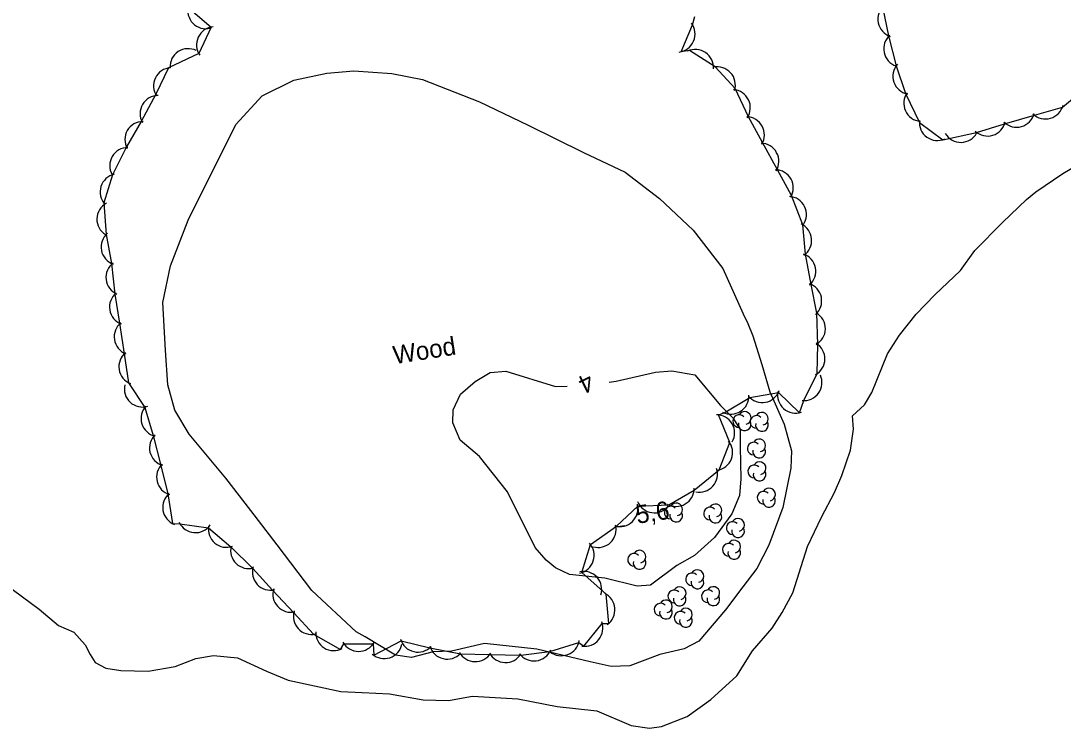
# Model space of a CAD drawing. Extents: x 643342 to 646936, y 5873857 to 5876103.
# Drawn here: x 643552.1 to 643724.9, y 5875255.8 to 5875373.1 of the extents above; entities that cross this region are included whole.
import ezdxf

# ---------------------------------------------------------------- set-up
doc = ezdxf.new("R2010")
doc.units = 0
for name, color, linetype in [('Niveau 2', 7, 'Continuous'), ('Niveau 3', 7, 'Continuous'), ('Niveau 4', 7, 'Continuous'), ('Niveau 44', 7, 'Continuous')]:
    doc.layers.add(name, color=color, linetype=linetype)

msp = doc.modelspace()

# ---------------------------------------------------------------- linework, layer by layer
at = {"layer": 'Niveau 2'}
for points in [[(643607.66, 5875271.79), (643600.32, 5875278.65), (643594.57, 5875286.24), (643590.17, 5875291.92), (643586.04, 5875297.27), (643579.96, 5875304.59), (643577.6, 5875308.55), (643576.42, 5875312.72), (643576.05, 5875318.5), (643575.62, 5875326.41), (643576.88, 5875332.45), (643579.8, 5875340.05), (643587.72, 5875355.89), (643592.06, 5875360.65), (643597.3, 5875363.22), (643602.78, 5875364.39), (643607.26, 5875364.77), (643613.59, 5875364.35), (643618.66, 5875363.35), (643628.11, 5875359.64), (643636.16, 5875355.81), (643645.33, 5875351.24), (643652.26, 5875348.02), (643657.97, 5875343.64), (643663.53, 5875338.4), (643668.46, 5875332.05), (643671.84, 5875324.5), (643672.57, 5875322.9)], [(643672.57, 5875322.9), (643673.45, 5875320.84), (643674.93, 5875316.1), (643676.26, 5875311.58), (643678.62, 5875306.2), (643679.83, 5875301.79), (643679.71, 5875298.93), (643678.37, 5875292.41), (643676.05, 5875286.16), (643674.11, 5875282.32), (643671.76, 5875279.27), (643668.87, 5875275.47), (643664.45, 5875270.23), (643662.06, 5875268.97), (643657.98, 5875268.03), (643653.03, 5875266.19), (643649.95, 5875266.06), (643646.44, 5875266.83), (643637.59, 5875268.94), (643628.96, 5875269.88), (643623.49, 5875268.6), (643620.41, 5875268.46), (643616.81, 5875267.56), (643614.17, 5875267.94), (643609.16, 5875270.96), (643607.66, 5875271.79)], [(643643.03, 5875281.28), (643640.68, 5875282.39), (643639.15, 5875283.68), (643637.31, 5875285.78), (643632.73, 5875295), (643628.08, 5875300.89), (643624.89, 5875303.58), (643623.7, 5875306.45), (643623.76, 5875308.58), (643624.96, 5875311.17), (643627.39, 5875313.27), (643629.87, 5875314.78), (643632.46, 5875315), (643640.73, 5875312.49), (643642.65, 5875312.55)], [(643663.81, 5875314.42), (643668.04, 5875309.33), (643670.12, 5875307.25), (643671.35, 5875305.34), (643671.35, 5875302.49), (643671.45, 5875297.17), (643671.21, 5875294.42), (643669.93, 5875291.35), (643667.06, 5875287.44), (643663.75, 5875284.43), (643660.81, 5875282.77), (643656.46, 5875279.56), (643654.22, 5875279.37), (643648.89, 5875280.7), (643643.03, 5875281.28)], [(643649.62, 5875313.19), (643650.74, 5875313.33), (643657.26, 5875314.82), (643659.97, 5875315.05), (643663.81, 5875314.42)]]:
    msp.add_lwpolyline(points, dxfattribs=at)
at = {"layer": 'Niveau 3'}
msp.add_line((643651.42, 5875289.29), (643652.21, 5875289.41), dxfattribs=at)
msp.add_line((643651.42, 5875289.29), (643652.21, 5875289.41), dxfattribs=at)
at = {"layer": 'Niveau 4'}
for points in [[(643691.93, 5875309.45), (643693.18, 5875311.46), (643695.73, 5875317.86), (643697.73, 5875320.99), (643700.53, 5875324.44), (643703.58, 5875327.66), (643707.88, 5875331.71), (643710.22, 5875335), (643714.82, 5875339.66), (643718.78, 5875343.44), (643720.34, 5875344.76), (643724.84, 5875347.75), (643728.46, 5875349.95)], [(643544.82, 5875283.14), (643555.09, 5875275.56), (643558.29, 5875272.86), (643560.87, 5875271.77), (643562.72, 5875269.66), (643563.56, 5875268.07), (643564.39, 5875266.71), (643566.13, 5875265.79), (643568.66, 5875265.41), (643573.19, 5875265.31), (643577.64, 5875266.04), (643581.09, 5875267.39), (643584.02, 5875267.88), (643587.98, 5875267.49), (643592.8, 5875265.28), (643596.37, 5875263.8), (643605.09, 5875261.91), (643608.68, 5875261.73), (643613.21, 5875261.52), (643618.76, 5875260.55), (643622.94, 5875260.43), (643626.92, 5875261.12), (643629.79, 5875261), (643634.45, 5875260.67), (643640.98, 5875259.44), (643647.58, 5875258.68), (643653.26, 5875256.3), (643656.27, 5875255.84), (643658.27, 5875256.12), (643662.53, 5875257.79), (643666.45, 5875260.61), (643670.76, 5875264.53), (643673.38, 5875268.68), (643676.64, 5875272.4), (643678.31, 5875275.03), (643680.06, 5875278.27), (643682.5, 5875285.96), (643684.83, 5875290.79), (643686.98, 5875294.89), (643688.16, 5875297.73), (643689.6, 5875301.89), (643690.13, 5875305.38), (643689.94, 5875307.62), (643691.93, 5875309.45)]]:
    msp.add_lwpolyline(points, dxfattribs=at)
at = {"layer": 'Niveau 44'}
for points in [[(643693.89, 5875400.62), (643694.24, 5875395.35), (643694.29, 5875390.5), (643694.26, 5875385.36), (643694.18, 5875380.51), (643694.94, 5875375.38), (643695.89, 5875370.62), (643697.19, 5875365.62), (643698.75, 5875361.02), (643701.03, 5875356.25), (643704.95, 5875353.38), (643710.53, 5875354.58), (643715.17, 5875356.01), (643720.11, 5875357.46), (643724.77, 5875358.79), (643728.77, 5875362.1)], [(643579.79, 5875375.28), (643583.61, 5875372.05), (643581.57, 5875367.65), (643576.54, 5875365.27), (643574.42, 5875360.9), (643572.01, 5875356.38), (643569.57, 5875352.18), (643567.26, 5875347.55), (643565.8, 5875342.92), (643566.2, 5875337.64), (643567.08, 5875332.87), (643567.65, 5875327.76), (643568.4, 5875322.97), (643569.19, 5875317.88), (643569.94, 5875313.09), (643572.6, 5875308.99), (643574, 5875304.34), (643575.29, 5875299.37), (643576.43, 5875294.66), (643577.23, 5875289.74), (643578.45, 5875289.69), (643583.16, 5875289.03), (643586.87, 5875285.9), (643590.51, 5875282.29), (643593.81, 5875278.73), (643597.3, 5875274.96), (643600.6, 5875271.4), (643605.06, 5875268.89), (643605.62, 5875269.81), (643610.48, 5875269.79), (643610.56, 5875267.91), (643615.13, 5875270.29), (643619.85, 5875269.16), (643624.93, 5875268.16), (643629.79, 5875268.02), (643634.97, 5875267.94), (643639.78, 5875268.52), (643644.58, 5875270.06), (643645.39, 5875269.41), (643648.46, 5875273.18), (643649.53, 5875273.2), (643649.12, 5875278.03), (643645.06, 5875281.63)], [(643645.06, 5875281.63), (643646.52, 5875286.26), (643650.84, 5875289.29), (643654.34, 5875292.65), (643659.5, 5875292.85), (643663.7, 5875295.28), (643667.85, 5875298.64), (643669.59, 5875303.17), (643667.72, 5875307.78), (643668.69, 5875308.08), (643672.91, 5875310.64), (643677.69, 5875311.5), (643681.17, 5875308.12), (643681.9, 5875310.13), (643684.09, 5875314.6), (643684.18, 5875319.45), (643684.05, 5875324.64), (643683.09, 5875329.4), (643682.14, 5875334.42), (643681.72, 5875339.26), (643679.84, 5875344.11), (643677.51, 5875348.37), (643675.05, 5875352.89), (643672.72, 5875357.15), (643670.47, 5875361.85), (643667.19, 5875365.43), (643662.9, 5875368.16), (643661.52, 5875367.96), (643663.41, 5875372.43)], [(643663.41, 5875372.43), (643663.82, 5875373.78)]]:
    msp.add_lwpolyline(points, dxfattribs=at)
for centre, radius, start, end in [((643582.74, 5875374.77), 3, 164.1537, 284.1317), ((643582.74, 5875374.77), 3, 164.1537, 284.1317), ((643582.74, 5875374.77), 3, 164.1537, 284.1317), ((643697.15, 5875373.35), 3, 131.2961, 251.274), ((643697.15, 5875373.35), 3, 131.2961, 251.274), ((643697.15, 5875373.35), 3, 131.2961, 251.274), ((643660.84, 5875370.88), 3, 277.0845, 37.0624), ((643660.84, 5875370.88), 3, 277.0845, 37.0624), ((643660.84, 5875370.88), 3, 277.0845, 37.0624), ((643584.19, 5875369.11), 3, 95.0938, 215.0717), ((643584.19, 5875369.11), 3, 95.0938, 215.0717), ((643584.19, 5875369.11), 3, 95.0938, 215.0717), ((643698.12, 5875368.44), 3, 131.2961, 251.274), ((643698.12, 5875368.44), 3, 131.2961, 251.274), ((643698.12, 5875368.44), 3, 131.2961, 251.274), ((643579.79, 5875365.47), 3, 63.1855, 183.1634), ((643579.79, 5875365.47), 3, 63.1855, 183.1634), ((643579.79, 5875365.47), 3, 63.1855, 183.1634), ((643663.9, 5875365.34), 3, 355.5807, 115.5586), ((643663.9, 5875365.34), 3, 355.5807, 115.5586), ((643663.9, 5875365.34), 3, 355.5807, 115.5586), ((643699.64, 5875363.89), 3, 138.696, 258.674), ((643699.64, 5875363.89), 3, 138.696, 258.674), ((643699.64, 5875363.89), 3, 138.696, 258.674), ((643577.07, 5875362.31), 3, 94.1708, 214.1488), ((643577.07, 5875362.31), 3, 94.1708, 214.1488), ((643577.07, 5875362.31), 3, 94.1708, 214.1488), ((643667.53, 5875362.45), 3, 342.4524, 102.4304), ((643667.53, 5875362.45), 3, 342.4524, 102.4304), ((643667.53, 5875362.45), 3, 342.4524, 102.4304), ((643574.83, 5875357.71), 3, 89.7917, 209.7696), ((643574.83, 5875357.71), 3, 89.7917, 209.7696), ((643574.83, 5875357.71), 3, 89.7917, 209.7696), ((643670.01, 5875358.68), 3, 325.9285, 85.9064), ((643670.01, 5875358.68), 3, 325.9285, 85.9064), ((643670.01, 5875358.68), 3, 325.9285, 85.9064), ((643701.45, 5875359.4), 3, 144.5519, 264.5298), ((643701.45, 5875359.4), 3, 144.5519, 264.5298), ((643701.45, 5875359.4), 3, 144.5519, 264.5298), ((643721.95, 5875359.82), 3, 225.9691, 345.9471), ((643721.95, 5875359.82), 3, 225.9691, 345.9471), ((643721.95, 5875359.82), 3, 225.9691, 345.9471), ((643672.34, 5875354.18), 3, 328.6401, 88.6181), ((643672.34, 5875354.18), 3, 328.6401, 88.6181), ((643672.34, 5875354.18), 3, 328.6401, 88.6181), ((643717.15, 5875358.44), 3, 225.9691, 345.9471), ((643717.15, 5875358.44), 3, 225.9691, 345.9471), ((643717.15, 5875358.44), 3, 225.9691, 345.9471), ((643572.31, 5875353.39), 3, 89.7917, 209.7696), ((643572.31, 5875353.39), 3, 89.7917, 209.7696), ((643572.31, 5875353.39), 3, 89.7917, 209.7696), ((643704.03, 5875356.24), 3, 173.8676, 293.8456), ((643704.03, 5875356.24), 3, 173.8676, 293.8456), ((643704.03, 5875356.24), 3, 173.8676, 293.8456), ((643712.33, 5875356.98), 3, 227.1427, 347.1206), ((643712.33, 5875356.98), 3, 227.1427, 347.1206), ((643712.33, 5875356.98), 3, 227.1427, 347.1206), ((643707.91, 5875355.94), 3, 210.9181, 330.896), ((643707.91, 5875355.94), 3, 210.9181, 330.896), ((643707.91, 5875355.94), 3, 210.9181, 330.896), ((643569.8, 5875349.07), 3, 89.7917, 209.7696), ((643569.8, 5875349.07), 3, 89.7917, 209.7696), ((643569.8, 5875349.07), 3, 89.7917, 209.7696), ((643674.74, 5875349.79), 3, 328.6401, 88.6181), ((643674.74, 5875349.79), 3, 328.6401, 88.6181), ((643674.74, 5875349.79), 3, 328.6401, 88.6181), ((643677.13, 5875345.4), 3, 328.6401, 88.6181), ((643677.13, 5875345.4), 3, 328.6401, 88.6181), ((643677.13, 5875345.4), 3, 328.6401, 88.6181), ((643568.21, 5875344.71), 3, 102.5963, 222.5742), ((643568.21, 5875344.71), 3, 102.5963, 222.5742), ((643568.21, 5875344.71), 3, 102.5963, 222.5742), ((643679.32, 5875340.97), 3, 326.304, 86.282), ((643679.32, 5875340.97), 3, 326.304, 86.282), ((643679.32, 5875340.97), 3, 326.304, 86.282), ((643567.67, 5875340.19), 3, 118.3373, 238.3153), ((643567.67, 5875340.19), 3, 118.3373, 238.3153), ((643567.67, 5875340.19), 3, 118.3373, 238.3153), ((643568.37, 5875335.58), 3, 130.4796, 250.4576), ((643568.37, 5875335.58), 3, 130.4796, 250.4576), ((643568.37, 5875335.58), 3, 130.4796, 250.4576), ((643680.17, 5875336.69), 3, 304.8821, 64.86), ((643680.17, 5875336.69), 3, 304.8821, 64.86), ((643680.17, 5875336.69), 3, 304.8821, 64.86), ((643680.86, 5875331.57), 3, 311.3707, 71.3487), ((643680.86, 5875331.57), 3, 311.3707, 71.3487), ((643680.86, 5875331.57), 3, 311.3707, 71.3487), ((643569.18, 5875330.55), 3, 126.8362, 246.8141), ((643569.18, 5875330.55), 3, 126.8362, 246.8141), ((643569.18, 5875330.55), 3, 126.8362, 246.8141), ((643681.84, 5875326.67), 3, 311.3707, 71.3487), ((643681.84, 5875326.67), 3, 311.3707, 71.3487), ((643681.84, 5875326.67), 3, 311.3707, 71.3487), ((643569.76, 5875325.64), 3, 128.9063, 248.8842), ((643569.76, 5875325.64), 3, 128.9063, 248.8842), ((643569.76, 5875325.64), 3, 128.9063, 248.8842), ((643682.45, 5875322.05), 3, 299.1658, 59.1438), ((643682.45, 5875322.05), 3, 299.1658, 59.1438), ((643682.45, 5875322.05), 3, 299.1658, 59.1438), ((643570.54, 5875320.7), 3, 128.9063, 248.8842), ((643570.54, 5875320.7), 3, 128.9063, 248.8842), ((643570.54, 5875320.7), 3, 128.9063, 248.8842), ((643682.37, 5875317.06), 3, 298.8671, 58.845), ((643682.37, 5875317.06), 3, 298.8671, 58.845), ((643682.37, 5875317.06), 3, 298.8671, 58.845), ((643571.31, 5875315.76), 3, 128.9063, 248.8842), ((643571.31, 5875315.76), 3, 128.9063, 248.8842), ((643571.31, 5875315.76), 3, 128.9063, 248.8842), ((643681.89, 5875313.13), 3, 264.2227, 24.2006), ((643681.89, 5875313.13), 3, 264.2227, 24.2006), ((643681.89, 5875313.13), 3, 264.2227, 24.2006), ((643572.23, 5875312.06), 3, 166.9826, 286.9605), ((643572.23, 5875312.06), 3, 166.9826, 286.9605), ((643572.23, 5875312.06), 3, 166.9826, 286.9605), ((643669.77, 5875310.88), 3, 242.8972, 2.8752), ((643669.77, 5875310.88), 3, 242.8972, 2.8752), ((643669.77, 5875310.88), 3, 242.8972, 2.8752), ((643674.99, 5875312.81), 3, 220.1496, 340.1276), ((643674.99, 5875312.81), 3, 220.1496, 340.1276), ((643674.99, 5875312.81), 3, 220.1496, 340.1276), ((643680.53, 5875311.05), 3, 168.3168, 288.2947), ((643680.53, 5875311.05), 3, 168.3168, 288.2947), ((643680.53, 5875311.05), 3, 168.3168, 288.2947), ((643574.99, 5875307.17), 3, 136.7512, 256.7292), ((643574.99, 5875307.17), 3, 136.7512, 256.7292), ((643574.99, 5875307.17), 3, 136.7512, 256.7292), ((643667.41, 5875304.79), 3, 330.0831, 90.061), ((643667.41, 5875304.79), 3, 330.0831, 90.061), ((643667.41, 5875304.79), 3, 330.0831, 90.061), ((643671.17, 5875306.72), 1.05, 44.1154, 269.804), ((643672.07, 5875307.25), 1.05, 282.2692, 149.7263), ((643674.02, 5875306.6), 1.05, 44.1154, 269.804), ((643674.92, 5875307.13), 1.05, 282.2692, 149.7263), ((643672.07, 5875306.2), 1.05, 166.9369, 29.6212), ((643674.92, 5875306.08), 1.05, 166.9369, 29.6212), ((643576.39, 5875302.29), 3, 133.6685, 253.6465), ((643576.39, 5875302.29), 3, 133.6685, 253.6465), ((643576.39, 5875302.29), 3, 133.6685, 253.6465), ((643667.07, 5875301.54), 3, 278.9047, 38.8827), ((643667.07, 5875301.54), 3, 278.9047, 38.8827), ((643667.07, 5875301.54), 3, 278.9047, 38.8827), ((643674.47, 5875302.71), 1.05, 282.2692, 149.7263), ((643673.57, 5875302.18), 1.05, 44.1154, 269.804), ((643674.47, 5875301.66), 1.05, 166.9369, 29.6212), ((643674.55, 5875298.93), 1.05, 282.2692, 149.7263), ((643577.57, 5875297.43), 3, 133.6685, 253.6465), ((643577.57, 5875297.43), 3, 133.6685, 253.6465), ((643577.57, 5875297.43), 3, 133.6685, 253.6465), ((643664.55, 5875297.94), 3, 258.5972, 18.5752), ((643664.55, 5875297.94), 3, 258.5972, 18.5752), ((643664.55, 5875297.94), 3, 258.5972, 18.5752), ((643673.65, 5875298.4), 1.05, 44.1154, 269.804), ((643674.55, 5875297.88), 1.05, 166.9369, 29.6212), ((643578.58, 5875292.42), 3, 129.2613, 249.2392), ((643578.58, 5875292.42), 3, 129.2613, 249.2392), ((643578.58, 5875292.42), 3, 129.2613, 249.2392), ((643660.71, 5875295.59), 3, 240.1405, 0.1184), ((643660.71, 5875295.59), 3, 240.1405, 0.1184), ((643660.71, 5875295.59), 3, 240.1405, 0.1184), ((643675.21, 5875294.04), 1.05, 44.1154, 269.804), ((643676.11, 5875294.57), 1.05, 282.2692, 149.7263), ((643651.37, 5875292.24), 3, 253.8014, 13.7793), ((643651.37, 5875292.24), 3, 253.8014, 13.7793), ((643651.37, 5875292.24), 3, 253.8014, 13.7793), ((643657.1, 5875294.53), 3, 202.0053, 321.9833), ((643657.1, 5875294.53), 3, 202.0053, 321.9833), ((643657.1, 5875294.53), 3, 202.0053, 321.9833), ((643660.71, 5875292.1), 1.05, 282.2692, 149.7263), ((643667.22, 5875291.94), 1.05, 282.2692, 149.7263), ((643676.11, 5875293.52), 1.05, 166.9369, 29.6212), ((643659.81, 5875291.57), 1.05, 44.1154, 269.804), ((643660.71, 5875291.05), 1.05, 166.9369, 29.6212), ((643666.32, 5875291.41), 1.05, 44.1154, 269.804), ((643667.22, 5875290.89), 1.05, 166.9369, 29.6212), ((643581.02, 5875291.24), 3, 205.0776, 325.0555), ((643581.02, 5875291.24), 3, 205.0776, 325.0555), ((643581.02, 5875291.24), 3, 205.0776, 325.0555), ((643647.76, 5875288.78), 3, 253.8014, 13.7793), ((643647.76, 5875288.78), 3, 253.8014, 13.7793), ((643647.76, 5875288.78), 3, 253.8014, 13.7793), ((643670.08, 5875289.01), 1.05, 44.1154, 269.804), ((643670.98, 5875289.54), 1.05, 282.2692, 149.7263), ((643586.15, 5875288.81), 3, 169.8403, 289.8183), ((643586.15, 5875288.81), 3, 169.8403, 289.8183), ((643586.15, 5875288.81), 3, 169.8403, 289.8183), ((643670.98, 5875288.49), 1.05, 166.9369, 29.6212), ((643589.84, 5875285.29), 3, 165.879, 285.857), ((643589.84, 5875285.29), 3, 165.879, 285.857), ((643589.84, 5875285.29), 3, 165.879, 285.857), ((643644.11, 5875284.47), 3, 282.6025, 42.5805), ((643644.11, 5875284.47), 3, 282.6025, 42.5805), ((643644.11, 5875284.47), 3, 282.6025, 42.5805), ((643669.44, 5875285.41), 1.05, 44.1154, 269.804), ((643670.34, 5875285.94), 1.05, 282.2692, 149.7263), ((643653.74, 5875283.75), 1.05, 44.1154, 269.804), ((643654.64, 5875284.28), 1.05, 282.2692, 149.7263), ((643670.34, 5875284.89), 1.05, 166.9369, 29.6212), ((643593.45, 5875281.71), 3, 162.82, 282.7979), ((643593.45, 5875281.71), 3, 162.82, 282.7979), ((643593.45, 5875281.71), 3, 162.82, 282.7979), ((643654.64, 5875283.23), 1.05, 166.9369, 29.6212), ((643645.37, 5875278.83), 3, 342.2461, 102.224), ((643645.37, 5875278.83), 3, 342.2461, 102.224), ((643645.37, 5875278.83), 3, 342.2461, 102.224), ((643663.34, 5875280.51), 1.05, 44.1154, 269.804), ((643664.24, 5875281.04), 1.05, 282.2692, 149.7263), ((643661.3, 5875278.21), 1.05, 282.2692, 149.7263), ((643664.24, 5875279.99), 1.05, 166.9369, 29.6212), ((643666.87, 5875278.23), 1.05, 282.2692, 149.7263), ((643596.85, 5875278.04), 3, 162.82, 282.7979), ((643596.85, 5875278.04), 3, 162.82, 282.7979), ((643596.85, 5875278.04), 3, 162.82, 282.7979), ((643647.56, 5875275.47), 3, 304.8751, 64.8531), ((643647.56, 5875275.47), 3, 304.8751, 64.8531), ((643647.56, 5875275.47), 3, 304.8751, 64.8531), ((643660.4, 5875277.68), 1.05, 44.1154, 269.804), ((643661.3, 5875277.16), 1.05, 166.9369, 29.6212), ((643665.97, 5875277.7), 1.05, 44.1154, 269.804), ((643666.87, 5875277.18), 1.05, 166.9369, 29.6212), ((643658.11, 5875275.49), 1.05, 44.1154, 269.804), ((643659.01, 5875276.02), 1.05, 282.2692, 149.7263), ((643662.33, 5875274.67), 1.05, 282.2692, 149.7263), ((643600.25, 5875274.37), 3, 162.82, 282.7979), ((643600.25, 5875274.37), 3, 162.82, 282.7979), ((643600.25, 5875274.37), 3, 162.82, 282.7979), ((643659.01, 5875274.97), 1.05, 166.9369, 29.6212), ((643661.43, 5875274.14), 1.05, 44.1154, 269.804), ((643662.33, 5875273.62), 1.05, 166.9369, 29.6212), ((643645.56, 5875272.41), 3, 260.9001, 20.8781), ((643645.56, 5875272.41), 3, 260.9001, 20.8781), ((643645.56, 5875272.41), 3, 260.9001, 20.8781), ((643603.95, 5875271.68), 3, 177.6437, 297.6217), ((643603.95, 5875271.68), 3, 177.6437, 297.6217), ((643603.95, 5875271.68), 3, 177.6437, 297.6217), ((643617.89, 5875271.44), 3, 196.6461, 316.6241), ((643617.89, 5875271.44), 3, 196.6461, 316.6241), ((643617.89, 5875271.44), 3, 196.6461, 316.6241), ((643608.05, 5875271.56), 3, 209.8247, 329.8027), ((643608.05, 5875271.56), 3, 209.8247, 329.8027), ((643608.05, 5875271.56), 3, 209.8247, 329.8027), ((643612.31, 5875270.36), 3, 228.4648, 348.4427), ((643612.31, 5875270.36), 3, 228.4648, 348.4427), ((643612.31, 5875270.36), 3, 228.4648, 348.4427), ((643622.76, 5875270.28), 3, 196.6461, 316.6241), ((643622.76, 5875270.28), 3, 196.6461, 316.6241), ((643622.76, 5875270.28), 3, 196.6461, 316.6241), ((643637.16, 5875269.98), 3, 216.9125, 336.8905), ((643637.16, 5875269.98), 3, 216.9125, 336.8905), ((643637.16, 5875269.98), 3, 216.9125, 336.8905), ((643641.68, 5875270.84), 3, 231.0496, 351.0276), ((643641.68, 5875270.84), 3, 231.0496, 351.0276), ((643641.68, 5875270.84), 3, 231.0496, 351.0276), ((643627.41, 5875269.86), 3, 208.384, 328.3619), ((643627.41, 5875269.86), 3, 208.384, 328.3619), ((643627.41, 5875269.86), 3, 208.384, 328.3619), ((643632.41, 5875269.71), 3, 208.384, 328.3619), ((643632.41, 5875269.71), 3, 208.384, 328.3619), ((643632.41, 5875269.71), 3, 208.384, 328.3619)]:
    msp.add_arc(centre, radius, start, end, dxfattribs=at)

# ---------------------------------------------------------------- texts
at = {"layer": 'Niveau 2'}
msp.add_text('4', height=3, rotation=205.8639, dxfattribs=at).set_placement((643646.17, 5875314.83))
at = {"layer": 'Niveau 3'}
msp.add_text('5,6  ', height=3, rotation=8.9405, dxfattribs=at).set_placement((643654.27, 5875289.7))
msp.add_text('5,6  ', height=3, rotation=8.9405, dxfattribs=at).set_placement((643654.27, 5875289.7))
at = {"layer": 'Niveau 44'}
msp.add_text('Wood', height=3, rotation=8.9405, dxfattribs=at).set_placement((643614.02, 5875316.16))

doc.saveas('drawing.dxf')
